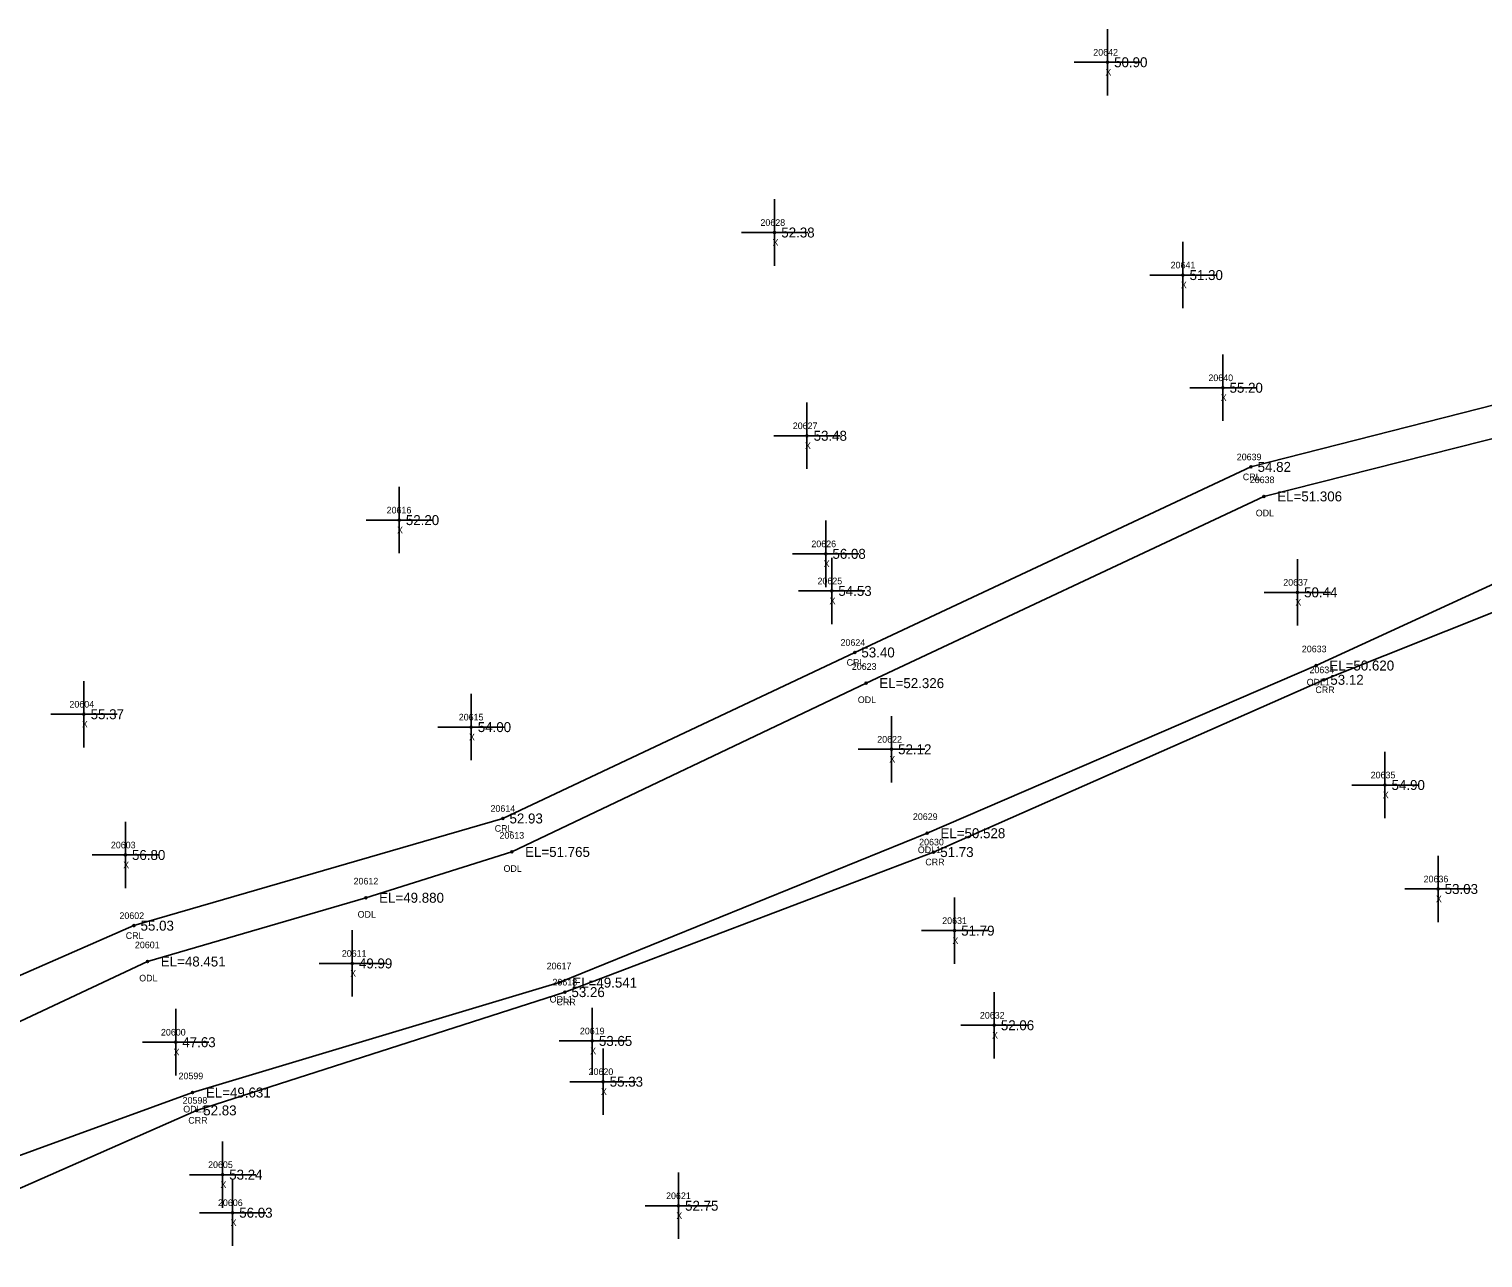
# Model space of a CAD drawing. Extents: x 2396547 to 2397655, y 770185 to 772649.
# Drawn here: x 2397158.9 to 2397377.8, y 771400.3 to 771585.4 of the extents above; entities that cross this region are included whole.
import ezdxf

# ---------------------------------------------------------------- set-up
doc = ezdxf.new("R2010")
doc.units = 0
for name, color, linetype in [('RD_EX_H2O', 7, 'Continuous'), ('RD_EX_H2O_txCode', 7, 'Continuous'), ('RD_EX_Misc', 7, 'Continuous'), ('RD_EX_Misc_txCode', 7, 'Continuous'), ('RD_EX_TX_H2O_ELEV', 7, 'Continuous'), ('RD_EX_TX_Misc_ELEV', 7, 'Continuous'), ('RD_SMD_Locator', 7, 'Continuous')]:
    doc.layers.add(name, color=color, linetype=linetype)

msp = doc.modelspace()

# ---------------------------------------------------------------- linework, layer by layer
at = {"layer": 'RD_EX_H2O'}
for points in [[(2397026.41, 771393.39), (2397070.16, 771405.14), (2397085.18, 771412.94), (2397115.64, 771424.52), (2397174.69, 771450.34), (2397230.25, 771466.48), (2397283.24, 771491.48), (2397342.91, 771519.42), (2397408.89, 771536.24), (2397447.46, 771546.47), (2397469.5, 771549.6), (2397497.19, 771541.27), (2397541.1, 771500.79)], [(2397042.3, 771381.6), (2397067.83, 771395.64), (2397118.36, 771417.53), (2397176.74, 771444.94), (2397209.62, 771454.54), (2397231.6, 771461.44), (2397284.94, 771486.86), (2397344.87, 771514.98), (2397410.89, 771531.68), (2397447.35, 771543.38), (2397470.51, 771546.83), (2397496.21, 771538.83), (2397538.93, 771498.41)], [(2397029.25, 771363), (2397046.94, 771364.51), (2397071.53, 771381.48), (2397124.8, 771403.82), (2397183.53, 771425.21), (2397238.71, 771441.76), (2397294.15, 771464.26), (2397352.71, 771489.51), (2397415.81, 771518.52), (2397439.88, 771522.42), (2397486.58, 771521.99), (2397528.15, 771484.04)], [(2397041.52, 771355.95), (2397076.78, 771367.04), (2397074.45, 771374.78), (2397101.55, 771387.62), (2397127, 771397.33), (2397184.13, 771422.52), (2397239.58, 771440.33), (2397295.12, 771461.42), (2397353.86, 771487.36), (2397417.93, 771512.91), (2397437.51, 771516.93), (2397483.94, 771516.4), (2397526.36, 771480.62)]]:
    msp.add_lwpolyline(points, dxfattribs=at)
at = {"layer": 'RD_EX_Misc'}
for p, q in [((2397321.3, 771575.36), (2397321.3, 771585.36)), ((2397316.3, 771580.36), (2397326.3, 771580.36)), ((2397271.18, 771549.72), (2397271.18, 771559.72)), ((2397266.18, 771554.72), (2397276.18, 771554.72)), ((2397332.66, 771543.31), (2397332.66, 771553.31)), ((2397327.66, 771548.31), (2397337.66, 771548.31)), ((2397338.68, 771526.34), (2397338.68, 771536.34)), ((2397333.68, 771531.34), (2397343.68, 771531.34)), ((2397276.05, 771519.11), (2397276.05, 771529.11)), ((2397271.05, 771524.11), (2397281.05, 771524.11)), ((2397214.64, 771506.41), (2397214.64, 771516.41)), ((2397209.64, 771511.41), (2397219.64, 771511.41)), ((2397278.88, 771501.33), (2397278.88, 771511.33)), ((2397273.88, 771506.33), (2397283.88, 771506.33)), ((2397279.77, 771495.75), (2397279.77, 771505.75)), ((2397349.91, 771495.53), (2397349.91, 771505.53)), ((2397274.77, 771500.75), (2397284.77, 771500.75)), ((2397344.91, 771500.53), (2397354.91, 771500.53)), ((2397167.17, 771477.18), (2397167.17, 771487.18)), ((2397225.47, 771475.24), (2397225.47, 771485.24)), ((2397162.17, 771482.18), (2397172.17, 771482.18)), ((2397288.77, 771471.9), (2397288.77, 771481.9)), ((2397220.47, 771480.24), (2397230.47, 771480.24)), ((2397283.77, 771476.9), (2397293.77, 771476.9)), ((2397363.08, 771466.52), (2397363.08, 771476.52)), ((2397358.08, 771471.52), (2397368.08, 771471.52)), ((2397173.4, 771455.98), (2397173.4, 771465.98)), ((2397168.4, 771460.98), (2397178.4, 771460.98)), ((2397371.08, 771450.86), (2397371.08, 771460.86)), ((2397298.27, 771444.59), (2397298.27, 771454.59)), ((2397366.08, 771455.86), (2397376.08, 771455.86)), ((2397207.58, 771439.65), (2397207.58, 771449.65)), ((2397293.27, 771449.59), (2397303.27, 771449.59)), ((2397202.58, 771444.65), (2397212.58, 771444.65)), ((2397304.24, 771430.34), (2397304.24, 771440.34)), ((2397180.98, 771427.79), (2397180.98, 771437.79)), ((2397243.71, 771427.98), (2397243.71, 771437.98)), ((2397299.24, 771435.34), (2397309.24, 771435.34)), ((2397175.98, 771432.79), (2397185.98, 771432.79)), ((2397238.71, 771432.98), (2397248.71, 771432.98)), ((2397245.34, 771421.84), (2397245.34, 771431.84)), ((2397240.34, 771426.84), (2397250.34, 771426.84)), ((2397188.04, 771407.84), (2397188.04, 771417.84)), ((2397256.69, 771403.16), (2397256.69, 771413.16)), ((2397183.04, 771412.84), (2397193.04, 771412.84)), ((2397189.55, 771402.11), (2397189.55, 771412.11)), ((2397184.55, 771407.11), (2397194.55, 771407.11)), ((2397251.69, 771408.16), (2397261.69, 771408.16))]:
    msp.add_line(p, q, dxfattribs=at)
at = {"layer": 'RD_SMD_Locator'}
for centre in [(2397321.3, 771580.36), (2397271.18, 771554.72), (2397332.66, 771548.31), (2397338.68, 771531.34), (2397276.05, 771524.11), (2397342.91, 771519.42), (2397344.87, 771514.98), (2397214.64, 771511.41), (2397278.88, 771506.33), (2397279.77, 771500.75), (2397349.91, 771500.53), (2397283.24, 771491.48), (2397352.71, 771489.51), (2397353.86, 771487.36), (2397284.94, 771486.86), (2397167.17, 771482.18), (2397225.47, 771480.24), (2397288.77, 771476.9), (2397363.08, 771471.52), (2397230.25, 771466.48), (2397294.15, 771464.26), (2397173.4, 771460.98), (2397231.6, 771461.44), (2397295.12, 771461.42), (2397209.62, 771454.54), (2397371.08, 771455.86), (2397174.69, 771450.34), (2397298.27, 771449.59), (2397176.74, 771444.94), (2397207.58, 771444.65), (2397238.71, 771441.76), (2397239.58, 771440.33), (2397304.24, 771435.34), (2397180.98, 771432.79), (2397243.71, 771432.98), (2397245.34, 771426.84), (2397183.53, 771425.21), (2397184.13, 771422.52), (2397188.04, 771412.84), (2397189.55, 771407.11), (2397256.69, 771408.16)]:
    msp.add_circle(centre, 0.15, dxfattribs=at)

# ---------------------------------------------------------------- texts
at = {"layer": 'RD_EX_H2O_txCode'}
for s, p in [('20639', (2397340.77, 771520.42)), ('CRL', (2397341.68, 771517.42)), ('20638', (2397342.73, 771516.98)), ('ODL', (2397343.63, 771511.98)), ('20624', (2397281.1, 771492.48)), ('20633', (2397350.57, 771491.51)), ('CRL', (2397282.02, 771489.48)), ('20623', (2397282.8, 771488.86)), ('ODL1', (2397351.3, 771486.51)), ('20634', (2397351.72, 771488.36)), ('CRR', (2397352.61, 771485.36)), ('ODL', (2397283.7, 771483.86)), ('20614', (2397228.39, 771467.48)), ('CRL', (2397229.02, 771464.48)), ('20629', (2397292, 771466.26)), ('20613', (2397229.74, 771463.44)), ('20630', (2397292.94, 771462.42)), ('ODL1', (2397292.74, 771461.26)), ('ODL', (2397230.35, 771458.44)), ('CRR', (2397293.87, 771459.42)), ('20612', (2397207.77, 771456.54)), ('20602', (2397172.51, 771451.34)), ('ODL', (2397208.38, 771451.54)), ('CRL', (2397173.46, 771448.34)), ('20601', (2397174.84, 771446.94)), ('20617', (2397236.85, 771443.76)), ('ODL', (2397175.49, 771441.94)), ('20618', (2397237.72, 771441.33)), ('ODL1', (2397237.3, 771438.76)), ('CRR', (2397238.33, 771438.33)), ('20599', (2397181.41, 771427.21)), ('20598', (2397182.02, 771423.52)), ('ODL1', (2397182.12, 771422.21)), ('CRR', (2397182.88, 771420.52))]:
    msp.add_text(s, height=1, dxfattribs=at).set_placement(p)
at = {"layer": 'RD_EX_Misc_txCode'}
for s, p in [('20642', (2397319.16, 771581.36)), ('X', (2397320.99, 771578.36)), ('20628', (2397269.04, 771555.72)), ('X', (2397270.86, 771552.72)), ('20641', (2397330.81, 771549.31)), ('X', (2397332.35, 771546.31)), ('20640', (2397336.5, 771532.34)), ('X', (2397338.36, 771529.34)), ('20627', (2397273.91, 771525.11)), ('X', (2397275.74, 771522.11)), ('20616', (2397212.75, 771512.41)), ('X', (2397214.32, 771509.41)), ('20626', (2397276.71, 771507.33)), ('X', (2397278.56, 771504.33)), ('20625', (2397277.63, 771501.75)), ('20637', (2397347.77, 771501.53)), ('X', (2397279.45, 771498.75)), ('X', (2397349.59, 771498.53)), ('20604', (2397164.98, 771483.18)), ('X', (2397166.85, 771480.18)), ('20615', (2397223.61, 771481.24)), ('X', (2397225.15, 771478.24)), ('20622', (2397286.63, 771477.9)), ('X', (2397288.45, 771474.9)), ('20635', (2397360.94, 771472.52)), ('X', (2397362.76, 771469.52)), ('20603', (2397171.22, 771461.98)), ('X', (2397173.08, 771458.98)), ('20636', (2397368.91, 771456.86)), ('X', (2397370.76, 771453.86)), ('20631', (2397296.41, 771450.59)), ('X', (2397297.95, 771447.59)), ('20611', (2397206, 771445.65)), ('X', (2397207.26, 771442.65)), ('20632', (2397302.09, 771436.34)), ('20600', (2397178.76, 771433.79)), ('20619', (2397241.85, 771433.98)), ('X', (2397303.92, 771433.34)), ('X', (2397180.66, 771430.79)), ('X', (2397243.4, 771430.98)), ('20620', (2397243.16, 771427.84)), ('X', (2397245.02, 771424.84)), ('20605', (2397185.86, 771413.84)), ('X', (2397187.72, 771410.84)), ('20606', (2397187.35, 771408.11)), ('20621', (2397254.83, 771409.16)), ('X', (2397256.37, 771406.16)), ('X', (2397189.24, 771405.11))]:
    msp.add_text(s, height=1, dxfattribs=at).set_placement(p)
at = {"layer": 'RD_EX_TX_H2O_ELEV'}
for s, p in [('54.82', (2397343.91, 771518.67)), ('EL=51.306', (2397346.87, 771514.23)), ('53.40', (2397284.24, 771490.73)), ('EL=50.620', (2397354.71, 771488.76)), ('EL=52.326', (2397286.94, 771486.11)), ('53.12', (2397354.86, 771486.61)), ('52.93', (2397231.25, 771465.73)), ('EL=50.528', (2397296.15, 771463.51)), ('EL=51.765', (2397233.6, 771460.69)), ('51.73', (2397296.12, 771460.67)), ('EL=49.880', (2397211.62, 771453.79)), ('55.03', (2397175.69, 771449.59)), ('EL=48.451', (2397178.74, 771444.19)), ('EL=49.541', (2397240.71, 771441.01)), ('53.26', (2397240.58, 771439.58)), ('EL=49.631', (2397185.53, 771424.46)), ('52.83', (2397185.13, 771421.77))]:
    msp.add_text(s, height=1.5, dxfattribs=at).set_placement(p)
at = {"layer": 'RD_EX_TX_Misc_ELEV'}
for s, p in [('50.90', (2397322.3, 771579.61)), ('52.38', (2397272.18, 771553.97)), ('51.30', (2397333.66, 771547.56)), ('55.20', (2397339.68, 771530.59)), ('53.48', (2397277.05, 771523.36)), ('52.20', (2397215.64, 771510.66)), ('56.08', (2397279.88, 771505.58)), ('54.53', (2397280.77, 771500)), ('50.44', (2397350.91, 771499.78)), ('55.37', (2397168.17, 771481.43)), ('54.00', (2397226.47, 771479.49)), ('52.12', (2397289.77, 771476.15)), ('54.90', (2397364.08, 771470.77)), ('56.80', (2397174.4, 771460.23)), ('53.03', (2397372.08, 771455.11)), ('51.79', (2397299.27, 771448.84)), ('49.99', (2397208.58, 771443.9)), ('52.06', (2397305.24, 771434.59)), ('47.63', (2397181.98, 771432.04)), ('53.65', (2397244.71, 771432.23)), ('55.33', (2397246.34, 771426.09)), ('53.24', (2397189.04, 771412.09)), ('52.75', (2397257.69, 771407.41)), ('56.03', (2397190.55, 771406.36))]:
    msp.add_text(s, height=1.5, dxfattribs=at).set_placement(p)

doc.saveas('drawing.dxf')
